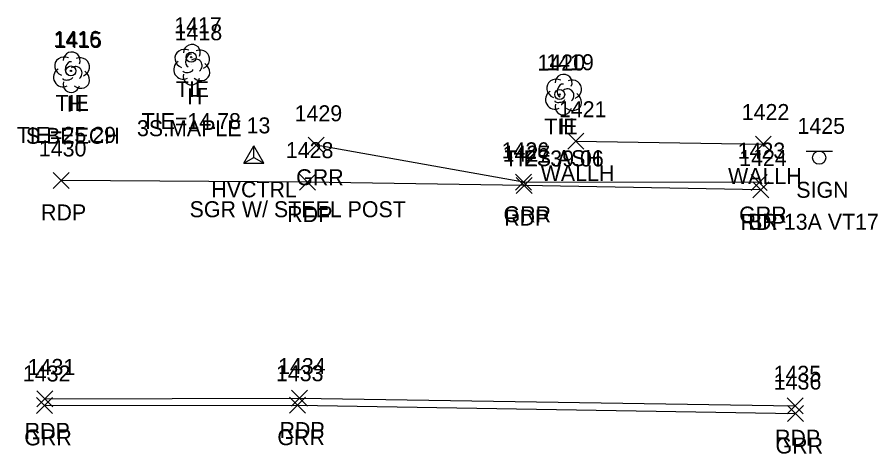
# Model space of a CAD drawing. Extents: x 1502119 to 1504100, y 606168 to 606406.
# Drawn here: x 1502788.9 to 1502896.5, y 606351.6 to 606406.3 of the extents above; entities that cross this region are included whole.
import ezdxf

# ---------------------------------------------------------------- set-up
doc = ezdxf.new("R2010")
doc.units = 0
for name, color, linetype in [('C_A', 7, 'Continuous'), ('C_C', 7, 'Continuous'), ('C_I', 7, 'Continuous'), ('CBP', 7, 'Continuous'), ('CPSM', 7, 'Continuous'), ('D_A', 7, 'Continuous'), ('D_I', 7, 'Continuous'), ('D_TIC', 7, 'Continuous'), ('DHW', 7, 'Continuous'), ('L_A', 7, 'Continuous'), ('L_C', 7, 'Continuous'), ('L_I', 7, 'Continuous'), ('LTD', 7, 'Continuous'), ('P_A', 7, 'Continuous'), ('P_I', 7, 'Continuous'), ('P_TIC', 7, 'Continuous'), ('PET', 7, 'Continuous'), ('R_A', 7, 'Continuous'), ('R_C', 7, 'Continuous'), ('R_I', 7, 'Continuous'), ('R_TIC', 7, 'Continuous'), ('RGR', 7, 'Continuous'), ('S_A', 7, 'Continuous'), ('S_C', 7, 'Continuous'), ('S_I', 7, 'Continuous'), ('SSGN', 7, 'Continuous')]:
    doc.layers.add(name, color=color, linetype=linetype)

msp = doc.modelspace()

# ---------------------------------------------------------------- linework, layer by layer
at = {"layer": 'CBP'}
for centre, radius in [((1502810.62, 606401.27), 0.625), ((1502810.62, 606401.27), 0.0833), ((1502795.58, 606399.55), 0.625), ((1502795.58, 606399.55), 0.0833), ((1502856.71, 606396.6), 0.625), ((1502856.71, 606396.6), 0.0833)]:
    msp.add_circle(centre, radius, dxfattribs=at)
at = {"layer": 'CPSM'}
for p, q in [((1502817.2, 606388.02), (1502818.45, 606390.18)), ((1502819.7, 606388.02), (1502818.45, 606390.18)), ((1502818.45, 606388.74), (1502818.45, 606390.18)), ((1502817.2, 606388.02), (1502818.45, 606388.74)), ((1502818.45, 606388.74), (1502818.45, 606388.74)), ((1502818.45, 606388.74), (1502819.7, 606388.02)), ((1502817.2, 606388.02), (1502819.7, 606388.02))]:
    msp.add_line(p, q, dxfattribs=at)
at = {"layer": 'D_TIC'}
for points in [[(1502857.74, 606389.76), (1502859.74, 606391.76)], [(1502859.74, 606389.76), (1502857.74, 606391.76)], [(1502881.18, 606389.41), (1502883.18, 606391.41)], [(1502883.18, 606389.41), (1502881.18, 606391.41)]]:
    msp.add_lwpolyline(points, dxfattribs=at)
at = {"layer": 'DHW'}
msp.add_lwpolyline([(1502858.74, 606390.76), (1502882.18, 606390.41)], dxfattribs=at)
at = {"layer": 'LTD'}
for p, q in [((1502795.64, 606399.44), (1502795.64, 606399.44)), ((1502795.64, 606399.44), (1502795.64, 606399.44)), ((1502810.67, 606400.39), (1502810.67, 606400.39)), ((1502810.67, 606400.39), (1502810.67, 606400.39)), ((1502857.17, 606396.64), (1502857.17, 606396.64)), ((1502857.17, 606396.64), (1502857.17, 606396.64))]:
    msp.add_line(p, q, dxfattribs=at)
for centre in [(1502810.72, 606401.82), (1502795.68, 606400.87), (1502857.21, 606398.08)]:
    msp.add_arc(centre, 1.05, 335.5272, 180.9563, dxfattribs=at)
for centre, major_axis, ratio, start_param, end_param in [((1502809.88, 606401.05), (1.21, -0.51), 0.895232, 1.570796, 4.712389), ((1502810.46, 606400.85), (-0.208, -0.792), 0.645439, 3.141593, 6.283185), ((1502811.71, 606400.97), (-1.14, -0.48), 0.949671, 1.570796, 4.712389), ((1502794.84, 606400.1), (1.21, -0.51), 0.895232, 1.570796, 4.712389), ((1502795.43, 606399.89), (-0.208, -0.792), 0.645439, 3.141593, 6.283185), ((1502796.68, 606400.02), (-1.14, -0.48), 0.949671, 1.570796, 4.712389), ((1502809.59, 606399.68), (0.58, -1.04), 0.959034, 3.141593, 6.283185), ((1502811.17, 606400.22), (-0.5, 0.667), 0.989748, 3.141593, 6.283185), ((1502811.67, 606399.55), (-1.09, 0.79), 0.841452, 1.570796, 4.712389), ((1502794.55, 606398.73), (0.58, -1.04), 0.959034, 3.141593, 6.283185), ((1502796.14, 606399.27), (-0.5, 0.667), 0.989748, 3.141593, 6.283185), ((1502796.64, 606398.6), (-1.09, 0.79), 0.841452, 1.570796, 4.712389), ((1502810.21, 606399.64), (-0.625, -0.083), 0.423636, 0, 3.141593), ((1502795.18, 606398.69), (-0.625, -0.083), 0.423636, 0, 3.141593), ((1502810.67, 606398.89), (0.26, 1.06), 0.942809, 1.570796, 4.712389), ((1502856.38, 606397.31), (1.21, -0.51), 0.895232, 1.570796, 4.712389), ((1502858.21, 606397.23), (-1.14, -0.48), 0.949671, 1.570796, 4.712389), ((1502795.64, 606397.94), (0.26, 1.06), 0.942809, 1.570796, 4.712389), ((1502856.96, 606397.1), (-0.208, -0.792), 0.645439, 3.141593, 6.283185), ((1502857.67, 606396.48), (-0.5, 0.667), 0.989748, 3.141593, 6.283185), ((1502856.08, 606395.93), (0.58, -1.04), 0.959034, 3.141593, 6.283185), ((1502858.17, 606395.81), (-1.09, 0.79), 0.841452, 1.570796, 4.712389), ((1502857.17, 606395.14), (0.26, 1.06), 0.942809, 1.570796, 4.712389), ((1502856.71, 606395.89), (-0.625, -0.083), 0.423636, 0, 3.141593)]:
    msp.add_ellipse(centre, major_axis=major_axis, ratio=ratio, start_param=start_param, end_param=end_param, dxfattribs=at)
at = {"layer": 'P_TIC'}
for points in [[(1502793.35, 606384.85), (1502795.35, 606386.85)], [(1502795.35, 606384.85), (1502793.35, 606386.85)], [(1502824.15, 606384.64), (1502826.15, 606386.64)], [(1502826.15, 606384.64), (1502824.15, 606386.64)], [(1502851.27, 606384.2), (1502853.27, 606386.2)], [(1502853.27, 606384.2), (1502851.27, 606386.2)], [(1502880.85, 606383.66), (1502882.85, 606385.66)], [(1502882.85, 606383.66), (1502880.85, 606385.66)], [(1502791.31, 606357.52), (1502793.31, 606359.52)], [(1502793.31, 606357.52), (1502791.31, 606359.52)], [(1502823.18, 606357.62), (1502825.18, 606359.62)], [(1502825.18, 606357.62), (1502823.18, 606359.62)], [(1502885.15, 606356.66), (1502887.15, 606358.66)], [(1502887.15, 606356.66), (1502885.15, 606358.66)]]:
    msp.add_lwpolyline(points, dxfattribs=at)
at = {"layer": 'PET'}
for points in [[(1502881.85, 606384.66), (1502852.27, 606385.2), (1502825.15, 606385.64), (1502794.35, 606385.85)], [(1502792.31, 606358.52), (1502824.18, 606358.62), (1502886.15, 606357.66)]]:
    msp.add_lwpolyline(points, dxfattribs=at)
at = {"layer": 'R_TIC'}
for points in [[(1502825.26, 606389.25), (1502827.26, 606391.25)], [(1502827.26, 606389.25), (1502825.26, 606391.25)], [(1502851.19, 606384.62), (1502853.19, 606386.62)], [(1502853.19, 606384.62), (1502851.19, 606386.62)], [(1502880.66, 606384.58), (1502882.66, 606386.58)], [(1502882.66, 606384.58), (1502880.66, 606386.58)], [(1502791.27, 606356.7), (1502793.27, 606358.7)], [(1502793.27, 606356.7), (1502791.27, 606358.7)], [(1502822.91, 606356.73), (1502824.91, 606358.73)], [(1502824.91, 606356.73), (1502822.91, 606358.73)], [(1502885.22, 606355.68), (1502887.22, 606357.68)], [(1502887.22, 606355.68), (1502885.22, 606357.68)]]:
    msp.add_lwpolyline(points, dxfattribs=at)
at = {"layer": 'RGR'}
for points in [[(1502881.66, 606385.58), (1502852.19, 606385.62), (1502826.26, 606390.25)], [(1502792.27, 606357.7), (1502823.91, 606357.73), (1502886.22, 606356.68)]]:
    msp.add_lwpolyline(points, dxfattribs=at)
at = {"layer": 'SSGN'}
for p, q in [((1502887.52, 606389.53), (1502890.85, 606389.53)), ((1502889.16, 606388.7), (1502889.16, 606388.7))]:
    msp.add_line(p, q, dxfattribs=at)
msp.add_circle((1502889.16, 606388.7), 0.833, dxfattribs=at)

# ---------------------------------------------------------------- texts
at = {"layer": 'C_A'}
for s, p in [('TIE', (1502808.7, 606396.27)), ('TIE', (1502793.66, 606394.55)), ('TIE', (1502854.79, 606391.6)), ('HVCTRL', (1502813.14, 606383.74))]:
    msp.add_text(s, height=2, dxfattribs=at).set_placement(p)
at = {"layer": 'C_C'}
for s, p in [('TIE=14.78', (1502804.42, 606392.27)), ('TIE=25.29', (1502788.8, 606390.55)), ('TIE=39.06', (1502849.81, 606387.6))]:
    msp.add_text(s, height=2, dxfattribs=at).set_placement(p)
at = {"layer": 'C_I'}
for s, p in [('1417', (1502808.49, 606404.27)), ('1416', (1502793.4, 606402.55)), ('1420', (1502853.93, 606399.6)), ('13', (1502817.55, 606391.74))]:
    msp.add_text(s, height=2, dxfattribs=at).set_placement(p)
at = {"layer": 'D_A'}
for p in [(1502854.33, 606385.76), (1502877.77, 606385.41)]:
    msp.add_text('WALLH', height=2, dxfattribs=at).set_placement(p)
at = {"layer": 'D_I'}
for s, p in [('1421', (1502856.61, 606393.76)), ('1422', (1502879.48, 606393.41))]:
    msp.add_text(s, height=2, dxfattribs=at).set_placement(p)
at = {"layer": 'L_A'}
for p in [(1502810.11, 606395.39), (1502795.07, 606394.44), (1502856.6, 606391.64)]:
    msp.add_text('H', height=2, dxfattribs=at).set_placement(p)
at = {"layer": 'L_C'}
for s, p in [('3S.MAPLE', (1502803.84, 606391.39)), ('S.BEECH', (1502789.95, 606390.44)), ('2S.ASH', (1502852.35, 606387.64))]:
    msp.add_text(s, height=2, dxfattribs=at).set_placement(p)
at = {"layer": 'L_I'}
for s, p in [('1418', (1502808.55, 606403.39)), ('1415', (1502793.51, 606402.44)), ('1419', (1502855.03, 606399.64))]:
    msp.add_text(s, height=2, dxfattribs=at).set_placement(p)
at = {"layer": 'P_A'}
for p in [(1502791.84, 606380.85), (1502822.64, 606380.64), (1502849.76, 606380.2), (1502879.34, 606379.66), (1502789.79, 606353.52), (1502821.67, 606353.62), (1502883.64, 606352.66)]:
    msp.add_text('RDP', height=2, dxfattribs=at).set_placement(p)
at = {"layer": 'P_I'}
for s, p in [('1430', (1502791.57, 606388.85)), ('1428', (1502822.46, 606388.64)), ('1427', (1502849.57, 606388.2)), ('1424', (1502879.16, 606387.66)), ('1431', (1502790.18, 606361.52)), ('1434', (1502821.49, 606361.62)), ('1435', (1502883.46, 606360.66))]:
    msp.add_text(s, height=2, dxfattribs=at).set_placement(p)
at = {"layer": 'R_A'}
for p in [(1502823.75, 606385.25), (1502849.68, 606380.62), (1502879.15, 606380.58), (1502789.75, 606352.7), (1502821.4, 606352.73), (1502883.71, 606351.68)]:
    msp.add_text('GRR', height=2, dxfattribs=at).set_placement(p)
at = {"layer": 'R_C'}
msp.add_text('SGR W/ STEEL POST', height=2, dxfattribs=at).set_placement((1502810.42, 606381.25))
at = {"layer": 'R_I'}
for s, p in [('1429', (1502823.56, 606393.25)), ('1426', (1502849.44, 606388.62)), ('1423', (1502878.97, 606388.58)), ('1433', (1502821.22, 606360.73)), ('1432', (1502789.57, 606360.7)), ('1436', (1502883.48, 606359.68))]:
    msp.add_text(s, height=2, dxfattribs=at).set_placement(p)
at = {"layer": 'S_A'}
msp.add_text('SIGN', height=2, dxfattribs=at).set_placement((1502886.3, 606383.68))
at = {"layer": 'S_C'}
msp.add_text('BR 13A VT17', height=2, dxfattribs=at).set_placement((1502880.28, 606379.68))
at = {"layer": 'S_I'}
msp.add_text('1425', height=2, dxfattribs=at).set_placement((1502886.45, 606391.68))

doc.saveas('drawing.dxf')
